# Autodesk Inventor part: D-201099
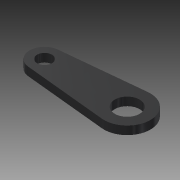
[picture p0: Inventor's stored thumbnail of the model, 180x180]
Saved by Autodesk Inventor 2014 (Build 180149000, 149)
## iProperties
Created: 2007-10
Part Number: D-201099
Document SubType Name: Modeling
Designer: TH
Density: 7.85 g/cm^3
Mass: 61.2 g
Surface Area: 44.7201 cm^2
Volume: 7.79617 cm^3
Material: Steel
Description: PIVOT PLATE
Appearance: Rubber - Black - Version 1.1
Component Category: Lower Component
Author: TH
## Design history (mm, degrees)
sketch "Sketch1"
  geometry: L1 (0, 0)-(-50, 0); L2 (-50.9, 8.955)-(-1.4, 13.93); L3 (-50.9, -8.955)-(-1.4, -13.93); A1 r 14 centre (0, 0) between (-1.4, -13.93) and (-1.4, 13.93); A2 r 9 centre (-50, 0) between (-50.9, 8.955) and (-50.9, -8.955); 1 further point
  constraints: 6 end point, 4 point on circle, 4 tangent, 2 centre point, 2 coincident, 1 horizontal
  dimensions: "d0" = 18 diameter of A2; "d1" = 28 diameter of A1; "d2" = 50 distance of point (0, 0) L1.end
extrude "Extrusion1" new body sketch "Sketch1" stored distance "d3" = 5; taper "d4" = 0 deg
sketch "Sketch2"
  geometry: A1 r 14 centre (0, 0) between (-1.4, -13.93) and (-1.4, 13.93) reference
hole "Hole1" sketch "Sketch2" at (0, 0) diameter "d5" = 15 (= Rod_Major_Diameter); stored, may be unused: countersink angle "d9" = 90 deg, drill point angle "d11" = 118 deg; dims "d6" = 6, "d7" = 4, "d8" = 2, "d10" = 8
sketch "Sketch3"
  geometry: A1 r 9 centre (-50, 0) between (-50.9, 8.955) and (-50.9, -8.955) reference
hole "Hole2" sketch "Sketch3" at (-50, 0) diameter "d12" = 9; stored, may be unused: countersink angle "d16" = 90 deg, drill point angle "d18" = 118 deg; dims "d13" = 6, "d14" = 4, "d15" = 2, "d17" = 8
workpoint "Work Point1"
  workaxis "Work Axis1"
workpoint "Work Point2"
  workaxis "Work Axis2"
node "200987" dims "d47" = 10
body "Solid1"
other parameters: "sa_eq_min" = 139698, "sa_eq_max" = 9220680, "sa_pmax_min" = -108063, "sa_pmax_max" = 8967840, "sa_pmin_min" = -8689420, "sa_pmin_max" = 96449.9, "sa_d_min" = 0.00021, "sa_d_max" = 0.01586, "sa_sf_min" = 22.4495, "d33" = 0, "d34" = -89714.6, "d35" = 0, "d36" = 0, "d37" = 89714.6, "d38" = 3415340, "d39" = -203486, "d40" = 682943, "d41" = 0, "d42" = 203062, "d43" = -683232, "d44" = 0, "d46" = 1.62473, "Rod_Major_Diameter" = 15
